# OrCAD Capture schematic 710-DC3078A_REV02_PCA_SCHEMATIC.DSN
size Custom; rev: 02; note: DEMO CIRCUIT 3078A
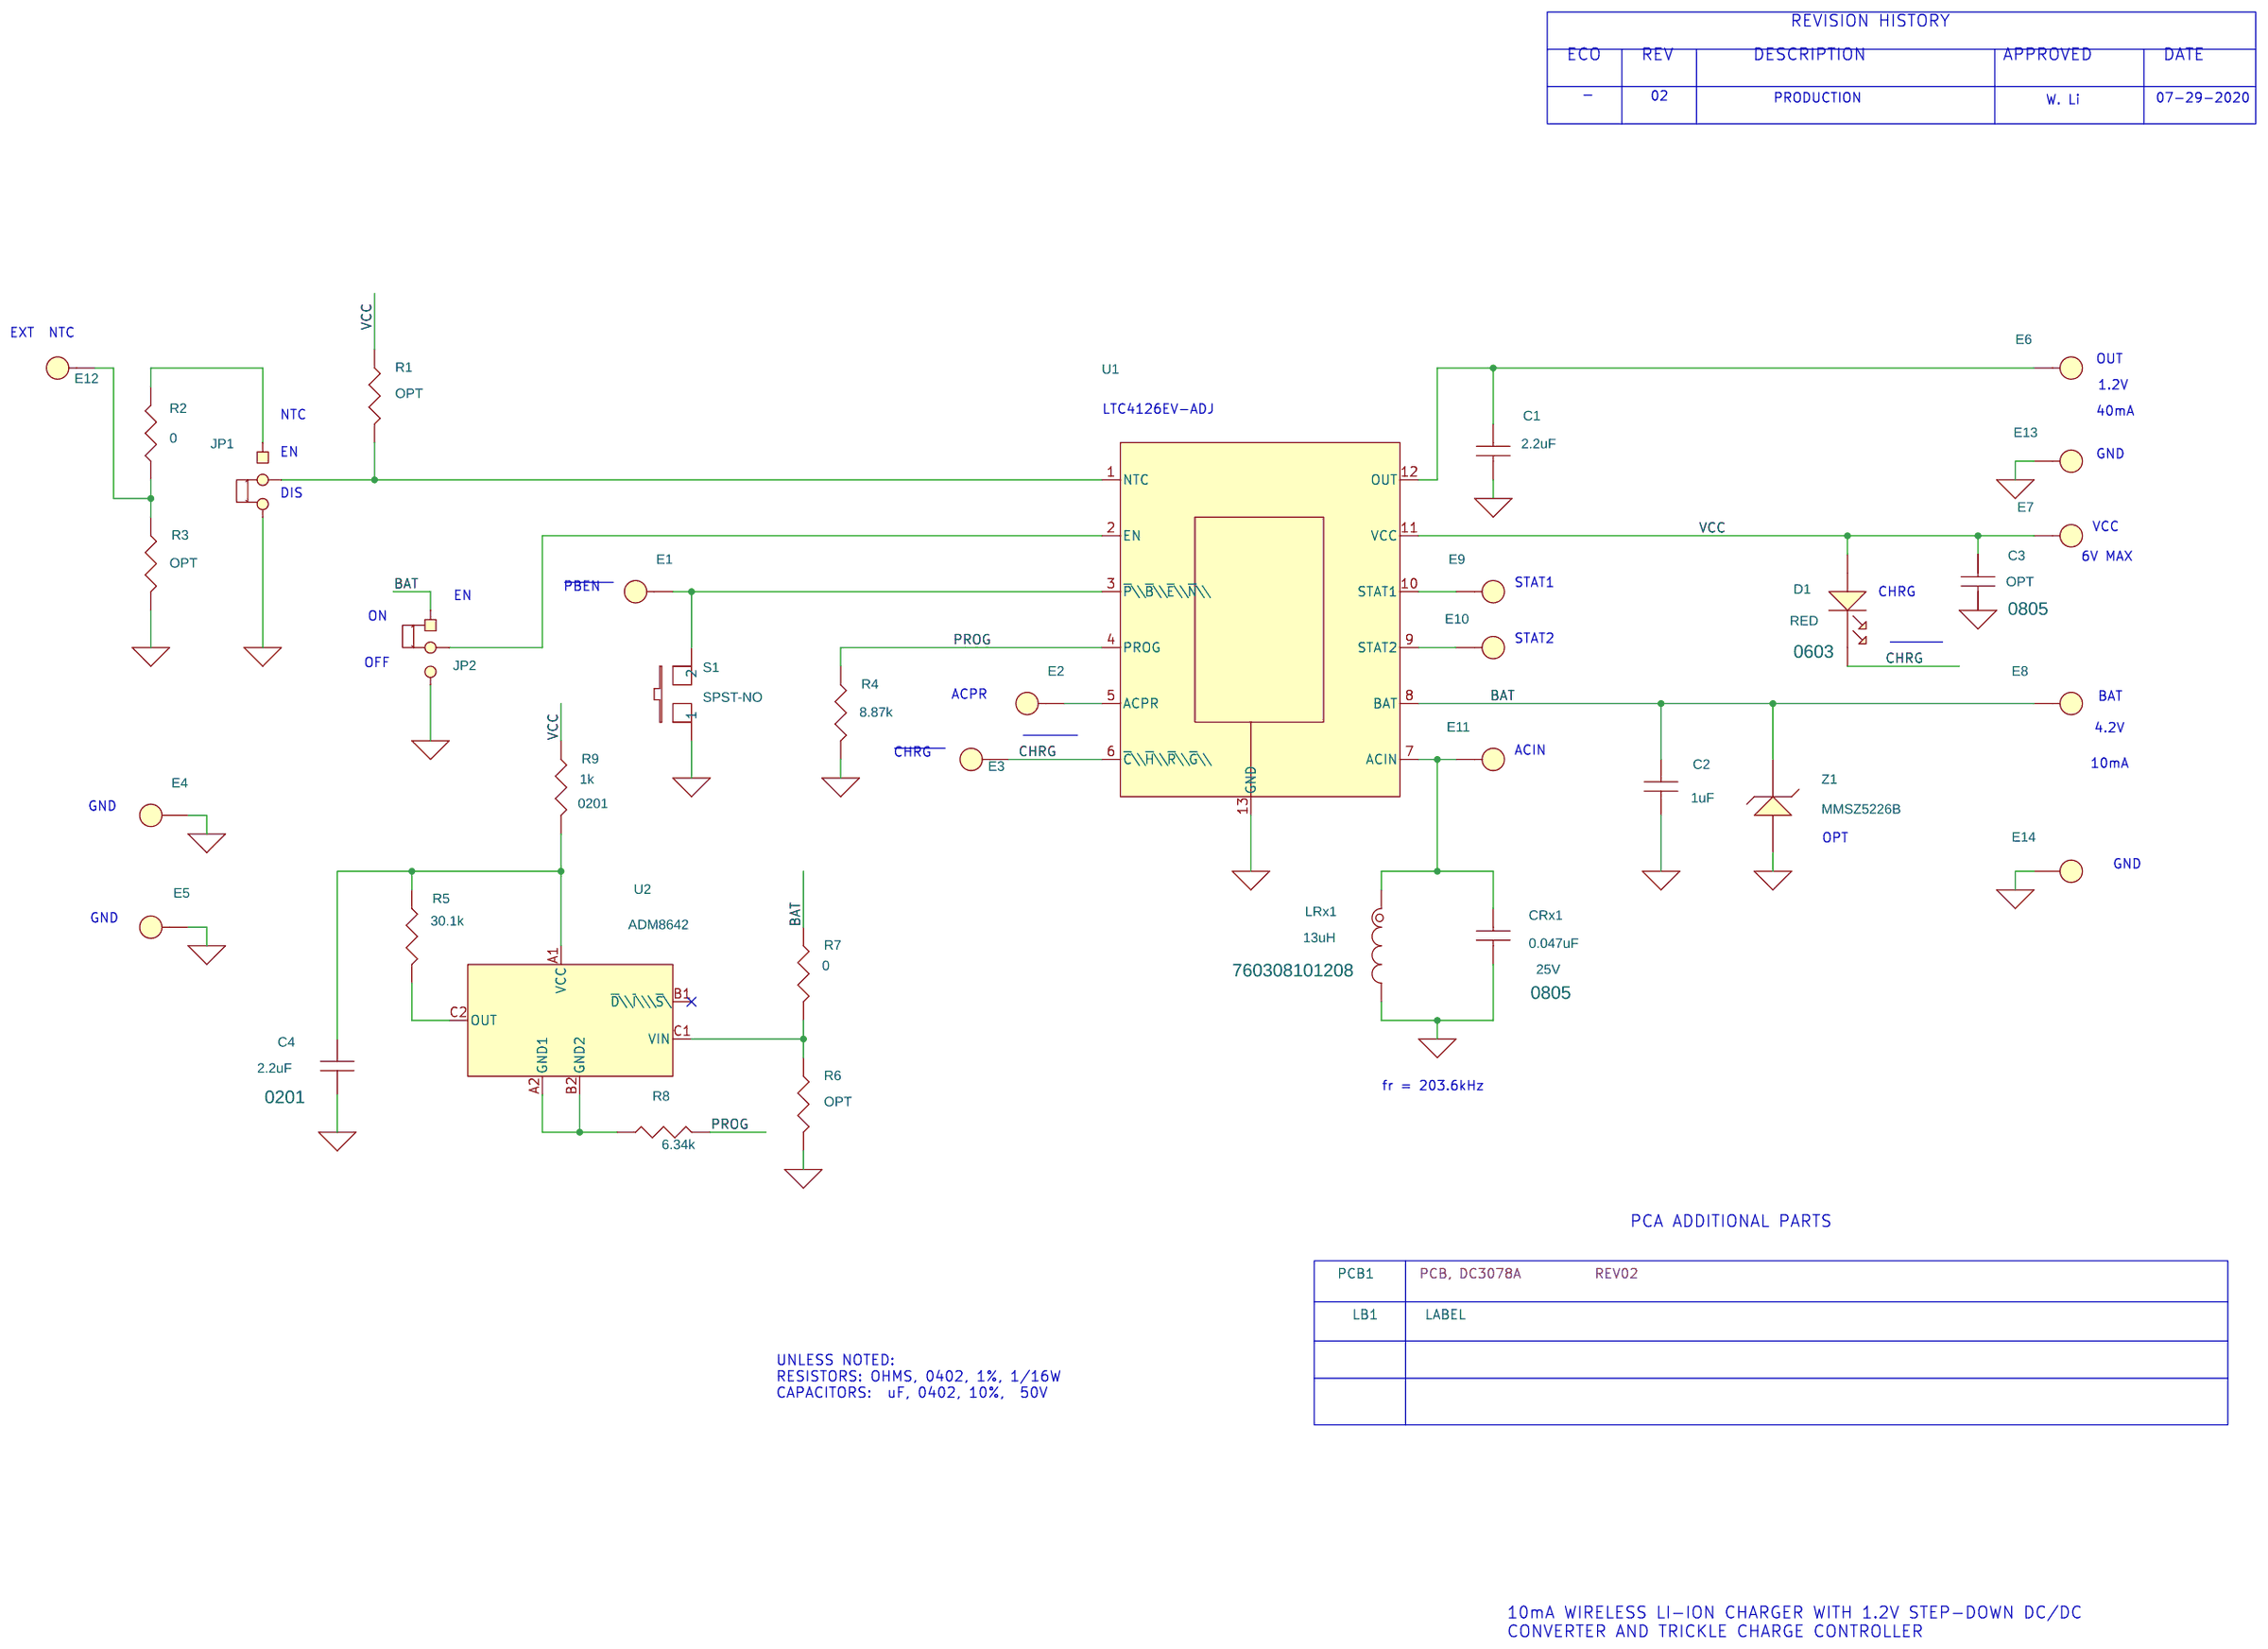
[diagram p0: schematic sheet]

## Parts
C1  2.2uF  [CC0402L]
C2  1uF  [CC0402L]
C3  OPT  [CC0805N]
C4  2.2uF  [CC0201M]
CRx1  0.047uF  [CC0805N]
D1  RED  [LED_0603]
E1  TEST POINT  [MILLMAX2308]
E2  TEST POINT  [MILLMAX2308]
E3  TEST POINT  [MILLMAX2308]
E4  TEST POINT  [MILLMAX2308]
E5  TEST POINT  [MILLMAX2308]
E6  TEST POINT  [MILLMAX2308]
E7  TEST POINT  [MILLMAX2308]
E8  TEST POINT  [MILLMAX2308]
E9  TEST POINT  [MILLMAX2308]
E10  TEST POINT  [MILLMAX2308]
E11  TEST POINT  [MILLMAX2308]
E12  TEST POINT  [MILLMAX2308]
E13  TEST POINT  [MILLMAX2308]
E14  TEST POINT  [MILLMAX2308]
JP1  HDR  [HD1X3-079]
JP2  HDR  [HD1X3-079]
LB1  LABEL  [895-0154_REV01]
LRx1  13uH  [WURTH-760308101208]
PCB1  PCB, DC3078A
R1  OPT  [CR0402L]
R2  0  [CR0402L]
R3  OPT  [CR0402L]
R4  8.87k  [CR0402L]
R5  30.1k  [CR0402L]
R6  OPT  [CR0402L]
R7  0  [CR0402L]
R8  6.34k  [CR0402N]
R9  1k  [CR0201N]
S1  SPST-NO  [WURTH-434111025826]
U1  LTC4126-ADJ-LQFN  [LTC-LQFN-12-1530]
U2  ADM8642  [ADI-CB-6-17]
XJP1  SHUNT
XJP3  SHUNT
Z1  MMSZ5226B  [SOD-123N]

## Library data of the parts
C1 = CAP: CAP.,2.2uF,X5R,16V,20%,0402; CLASS: DISCRETE; Dielectric Type: X5R; FPLIST: CC0402N,CC0402L,CC0402M; Inventory Qty: 52665; Manufacturer: TDK; Manufacturer PN: C1005X5R1C225M050BC; PART_NUMBER: 150-3242; Package Size: 0402; Package Type: SMD; Rated Voltage: 16V; Tolerance: 20%
C2 = CAP: CAP.,1uF,X5R,16V,10%,0402; CLASS: DISCRETE; Dielectric Type: X5R; Inventory Qty: 37068; Manufacturer: AVX; Manufacturer PN: 0402YD105KAT2A; PART_NUMBER: 150-0250; Package Size: 0402; Rated Voltage: 16V; Tolerance: 10%
C3 = CAP: CAP., OPTION, 0805; CLASS: DISCRETE; PART_NUMBER: 150-3036; Package Size: 0805; Package Type: SMD
C4 = CAP: CAP.,2.2uF,X5R,6.3V,20%,0201; CLASS: DISCRETE; Dielectric Type: X5R; Inventory Qty: 0; Manufacturer: MURATA; Manufacturer PN: GRM033R60J225ME47D; PART_NUMBER: 150-1833; Package Size: 0201; Package Type: Surface Mount, MLCC; Rated Voltage: 6.3V; Temperature Coefficient: X5R; Tolerance: 20%
CRx1 = CAP: CAP.,0.047uF,C0G,25V,5%,0805,AEC-Q200; CLASS: DISCRETE; Dielectric Type: C0G; FPLIST: CC0805N,CC0805L,CC0805M; Inventory Qty: 9654; Manufacturer: KEMET; Manufacturer PN: C0805C473J3GACAUTO; PART_NUMBER: 150-3226; Package Size: 0805; Rated Voltage: 25V; Tolerance: 5%
D1 = LED_ALT: LED,RED,WATER-CLEAR,0603; CLASS: DISCRETE; Inventory Qty: 15266; Manufacturer: LITE-ON; Manufacturer PN: LTST-C193KRKT-5A; PART_NUMBER: 270-0070; Package Size: 0603 (1608 Metric); Package Type: 0603
E1-E14 = TEST_POINT_.156_MILL-MAX_2308: TEST POINT,TURRET,0.064" MTG. HOLE,PCB 0.062" THK; CLASS: IO; Inventory Qty: 917580; Manufacturer: MILL-MAX; Manufacturer PN: 2308-2-00-80-00-00-07-0; PART_NUMBER: 260-0004
JP1 JP2 = 3_PIN_HEADER_.079_SINGLE_ROW_D: CONN.,HDR,MALE,1x3,2mm,VERT,ST,THT; CLASS: IO; Inventory Qty: 24133; Manufacturer: Wurth Elektronik; Manufacturer PN: 62000311121; PART_NUMBER: 250-0484
LB1 = BLANK_LABEL: LABEL SPEC, DEMO BOARD SERIAL NUMBER; Inventory Qty: 0; Manufacturer: BRADY; Manufacturer PN: THT-96-717-10; PART_NUMBER: 895-0154
LRx1 = WURTH_Rx_Coil: IND.,13uH,WIRELESS CHRG. COIL RX. Qi,10%,0.8A,500mOHMS,10mm Dia x 1.68mm H,1 COIL,1 LAYER; CLASS: DISCRETE; Inventory Qty: 1006; Manufacturer: Wurth Elektronik; Manufacturer PN: 760308101208; PART_NUMBER: 200-0330; Package Size: 10mm Dia x 1.68mm H; Tolerance: 10%
PCB1 = BLANK_PCB_PART: BOM Notes: REV02; CLASS: DISCRETE; Inventory Qty: 0; Manufacturer: ADI APPROVED SUPPLIER; Manufacturer PN: 600-DC3078A; PART_NUMBER: 600-DC3078A
R1 R3 R6 = RES: RES., OPTION, 0402; CLASS: DISCRETE; PART_NUMBER: 100-0357; Package Size: 0402
R2 = RES: RES.,0 OHM,5%,1/16W,0402; CLASS: DISCRETE; FPLIST: CR0402N,CR0402L,CR0402M; Inventory Qty: 10145; Manufacturer: ROHM; Manufacturer PN: MCR01MZPJ000; PART_NUMBER: 100-0194; Package Size: 0402; Rated Power: 1/16W; Tolerance: 5%
R4 = RES: RES.,8.87k OHMS,1%,1/16W,0402,AEC-Q200; CLASS: DISCRETE; FPLIST: CR0402N,CR0402L,CR0402M; Inventory Qty: 20000; Manufacturer: ROHM; Manufacturer PN: MCR01MZPF8871; PART_NUMBER: 100-0010; Package Size: 0402; Rated Power: 1/16W; Temperature Coefficient: 100ppm/C; Tolerance: 1%
R5 = RES: RES.,30.1k OHMS,1%,1/16W,0402,AEC-Q200; CLASS: DISCRETE; FPLIST: CR0402N,CR0402L,CR0402M; Inventory Qty: 83026; Manufacturer: NIC; Manufacturer PN: NRC04F3012TRF; PART_NUMBER: 100-2935; Package Size: 0402; Rated Power: 1/16W; Temperature Coefficient: 100ppm; Tolerance: 1%
R7 = RES: RES.,0 OHM,1/16W,0402; CLASS: DISCRETE; Inventory Qty: 136309; Manufacturer: NIC; Manufacturer PN: NRC04ZOTRF; PART_NUMBER: 100-0025; Package Size: 0402; Rated Power: 1/16W
R8 = RES: RES.,6.34k OHMS,1%,1/16W,0402,AEC-Q200; CLASS: DISCRETE; FPLIST: CR0402N,CR0402L,CR0402M; Inventory Qty: 0; Manufacturer: VISHAY; Manufacturer PN: CRCW04026K34FKED; PART_NUMBER: 100-2703; Package Size: 0402; Rated Power: 1/16W; Temperature Coefficient: 100ppm/C; Tolerance: 1%
R9 = RES: RES.,1k OHM,5%,1/20W,0201,AEC-Q200; CLASS: DISCRETE; Inventory Qty: 0; Manufacturer: PANASONIC; Manufacturer PN: ERJ1GNJ102C; PART_NUMBER: 100-1739; Package Size: 0201; Rated Power: 1/20W; Temperature Coefficient: +/-200ppm; Tolerance: 5%
S1 = SW_PUSHBUTTON_2PIN: SWITCH,TACTILE,SPST-NO,0.05A,12VDC,SMD,6.0x3.8x2.5mm,WHITE; CLASS: DISCRETE; Inventory Qty: 1598; Manufacturer: WURTH ELEKTRONIK; Manufacturer PN: 434111025826; PART_NUMBER: 430-0050
U1 = LTC4126-ADJ-LQFN: IC,Li-ion Charger with Step-Down Reg. for Hearing Aids with Adj. Current,LQFN-12; CLASS: IC; Inventory Qty: 0; Manufacturer: ANALOG DEVICES; Manufacturer PN: LTC4126EV-ADJ#PBF; PART_NUMBER: LTC4126EV-ADJ#PBF; Package Type: LQFN-12
U2 = ADM8642-CB-6-17: IC,Ultralow Pwr Voltage Detector,6-Ball WLCSP; CLASS: IC; Inventory Qty: 0; Manufacturer: ANALOG DEVICES; Manufacturer PN: ADM8642T100ACBZ-R7; PART_NUMBER: ADM8642T100ACBZ-R7; Package Size: 6-WFBGA, CSPBGA; Package Type: 6-Ball WLCSP
XJP1 XJP3 = CONN_SHUNT_2_POS_2mm: CONN.,SHUNT,FEMALE,2 POS,2mm; CLASS: IO; Inventory Qty: 68504; Manufacturer: Wurth Elektronik; Manufacturer PN: 60800213421; PART_NUMBER: 250-0485
Z1 = ZENER_ALT: DIODE,ZENER,3.3V,500mW,SOD-123; CLASS: DISCRETE; Inventory Qty: 0; Manufacturer: DIODES INC.; Manufacturer PN: MMSZ5226B-7-F; PART_NUMBER: 210-0315; Package Size: SOD-123; Package Type: SOD-123; Rated Voltage: 3.3V; Rated Voltage or Zener Voltage: 3.3V

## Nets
GND_SIGNAL: C1.2 C2.2 C3.2 C4.2 CRx1.2 E4.1(A) E5.1(A) E13.1(A) E14.1(A) JP1.3 JP2.3 LRx1.2 R3.2 R4.2 R6.2 S1.1 U1.13(GND) Z1.2(A)
VCC: C3.1 D1.2(ANODE) E7.1(A) R1.1 R9.1 U1.11(VCC)
BAT: C2.1 E8.1(A) JP2.1 R7.1 U1.8(BAT) Z1.1(C)
CHRG: D1.1(CATHODE) E3.1(A) U1.6(~{C}\\~{H}\\~{R}\\~{G}\\)
PROG: R4.1 R8.2 U1.4(PROG)
N16883772: CRx1.1 E11.1(A) LRx1.1 U1.7(ACIN)
N16884708: JP2.2 U1.2(EN)
N16885454: C1.1 E6.1(A) U1.12(OUT)
N16892377: E2.1(A) U1.5(ACPR)
N16892541: E9.1(A) U1.10(STAT1)
N16892544: E10.1(A) U1.9(STAT2)
N16892991: E1.1(A) S1.2 U1.3(~{P}\\~{B}\\~{E}\\~{N}\\)
N16900627: JP1.2 R1.2 U1.1(NTC)
N16920791: JP1.1 R2.2
N16920800: E12.1(A) R2.1 R3.1
N16934023: C4.1 R5.1 R9.2 U2.A1(VCC)
N16934084: R5.2 U2.C2(OUT)
N16934100: R8.1 U2.A2(GND1) U2.B2(GND2)
N16934135: R6.1 R7.2 U2.C1(VIN)

Not connected (* = marked no-connect by the designer): U2 B1(~{D}\\~{I}\\\~{S}\)*

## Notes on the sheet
- REVISION HISTORY
- ECO
- REV
- DESCRIPTION
- APPROVED
- DATE
- -
- 02
- PRODUCTION
- W. Li
- 07-29-2020
- EXT  NTC
- OUT
- 1.2V
- NTC
- LTC4126EV-ADJ
- 40mA
- EN
- GND
- DIS
- VCC
- 6V MAX
- EN
- PBEN
- STAT1
- CHRG
- ON
- STAT2
- OFF
- ACPR
- BAT
- 4.2V
- CHRG
- ACIN
- 10mA
- GND
- OPT
- GND
- GND
- fr = 203.6kHz
- PCA ADDITIONAL PARTS
- UNLESS NOTED:
  RESISTORS: OHMS, 0402, 1%, 1/16W
  CAPACITORS:  uF, 0402, 10%,  50V
- 10mA WIRELESS LI-ION CHARGER WITH 1.2V STEP-DOWN DC/DC
  CONVERTER AND TRICKLE CHARGE CONTROLLER
